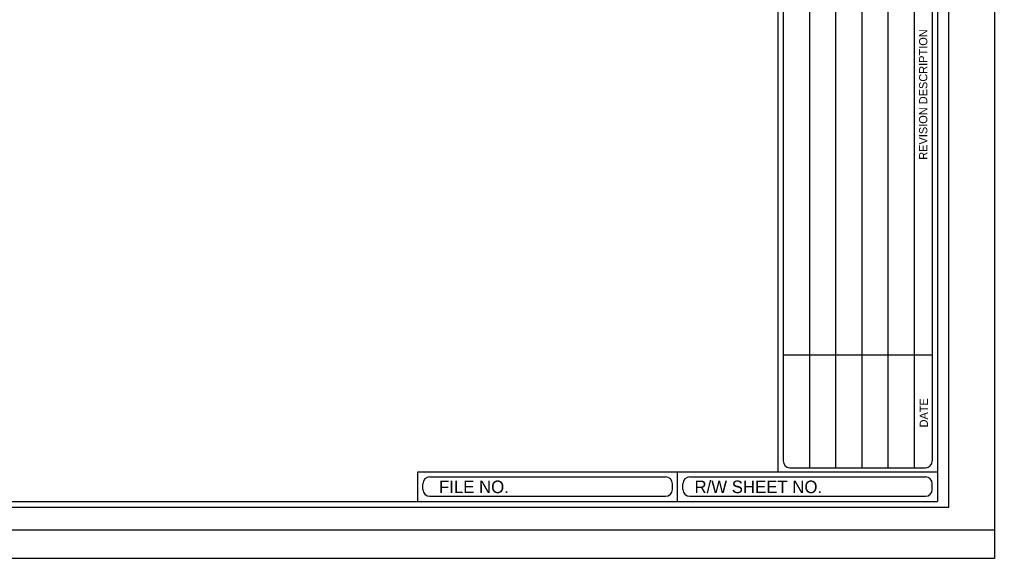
# Model space of a CAD drawing. Extents: x -0.21 to 2.64, y -0.06 to 1.81.
# Drawn here: x 1.929 to 2.642, y -0.042 to 0.352 of the extents above; entities that cross this region are included whole.
import ezdxf

# ---------------------------------------------------------------- set-up
doc = ezdxf.new("R2010")
doc.units = 0
for name, color, linetype in [('Plot Border', 7, 'Continuous'), ('Plot Border 2', 7, 'Continuous'), ('Sheet Border', 7, 'Continuous')]:
    doc.layers.add(name, color=color, linetype=linetype)

msp = doc.modelspace()

# ---------------------------------------------------------------- linework, layer by layer
at = {"layer": 'Plot Border'}
for points in [[(-0.19167, 1.79167), (2.64167, 1.79167), (2.64167, -0.04167), (-0.19167, -0.04167)], [(2.60833, 1.75417), (-0.14167, 1.75417), (-0.14167, -0.00417), (2.60833, -0.00417)]]:
    msp.add_lwpolyline(points, close=True, dxfattribs=at)
at = {"layer": 'Plot Border 2'}
msp.add_lwpolyline([(-0.19167, 1.77083), (2.64167, 1.77083), (2.64167, -0.02083), (-0.19167, -0.02083)], close=True, dxfattribs=at)
at = {"layer": 'Sheet Border'}
for p, q in [((2.48333, 1.75), (2.48333, 0.02183)), ((2.6, 1.75), (2.6, 0)), ((2.50634, 0.57121), (2.50634, 0.02475)), ((2.52549, 0.57121), (2.52549, 0.02475)), ((2.54464, 0.57121), (2.54464, 0.02475)), ((2.56379, 0.57121), (2.56379, 0.02475)), ((2.58294, 0.57121), (2.58294, 0.02475)), ((2.48719, 0.5663), (2.48719, 0.0297)), ((2.59615, 0.5663), (2.59615, 0.0297)), ((2.48719, 0.1073), (2.59615, 0.1073)), ((2.22, 0), (2.22, 0.02183)), ((2.41, 0), (2.41, 0.02183)), ((2.49214, 0.02475), (2.5912, 0.02475)), ((2.22883, 0.018), (2.40117, 0.018)), ((2.41883, 0.018), (2.59117, 0.018)), ((2.22383, 0.00883), (2.22383, 0.013)), ((2.40617, 0.00883), (2.40617, 0.013)), ((2.41383, 0.00883), (2.41383, 0.013)), ((2.59617, 0.00883), (2.59617, 0.013)), ((2.22883, 0.00383), (2.40117, 0.00383)), ((2.41883, 0.00383), (2.59117, 0.00383)), ((-0.025, 0), (2.6, 0))]:
    msp.add_line(p, q, dxfattribs=at)
msp.add_lwpolyline([(2.22, 0.02183), (2.6, 0.02183)], dxfattribs=at)
for centre, radius, start, end in [((2.49213, 0.02971), 0.00495, 180, 270), ((2.59118, 0.02971), 0.00495, 270, 0), ((2.22883, 0.013), 0.005, 90, 180), ((2.40117, 0.013), 0.005, 0, 90), ((2.41883, 0.013), 0.005, 90, 180), ((2.59117, 0.013), 0.005, 0, 90), ((2.22883, 0.00883), 0.005, 180, 270), ((2.40117, 0.00883), 0.005, 270, 0), ((2.41883, 0.00883), 0.005, 180, 270), ((2.59117, 0.00883), 0.005, 270, 0)]:
    msp.add_arc(centre, radius, start, end, dxfattribs=at)

# ---------------------------------------------------------------- texts
for s, p in [('REVISION DESCRIPTION', (2.59254, 0.24993)), ('DATE', (2.59298, 0.05419))]:
    msp.add_text(s, height=0.006, rotation=90, dxfattribs=at).set_placement(p)
for s, height, p in [('FILE NO.', 0.009167, (2.23558, 0.00615)), ('R/W SHEET NO.', 0.0091667, (2.42236, 0.00615))]:
    msp.add_text(s, height=height, dxfattribs=at).set_placement(p)

doc.saveas('drawing.dxf')
